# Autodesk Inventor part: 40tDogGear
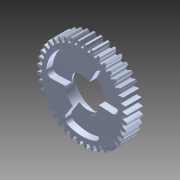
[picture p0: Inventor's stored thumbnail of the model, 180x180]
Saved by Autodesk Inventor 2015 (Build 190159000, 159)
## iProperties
Created: 2014-11
Part Number: 40tDogGear
Material: Aluminum 6061
Document SubType Name: Modeling
Designer: Michael
Density: 2.71 g/cm^3
Appearance: Aluminum - Flat
Title: 217-3417-STEP.STEP
Description: STEP AP214
Creation Date: 2013-12-09
Sending System: SolidWorks 2013
Preprocessor: SwSTEP 2.0
Author: Michael
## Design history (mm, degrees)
node "40tDogGear1"
node "BackBore"
node "Base1"
